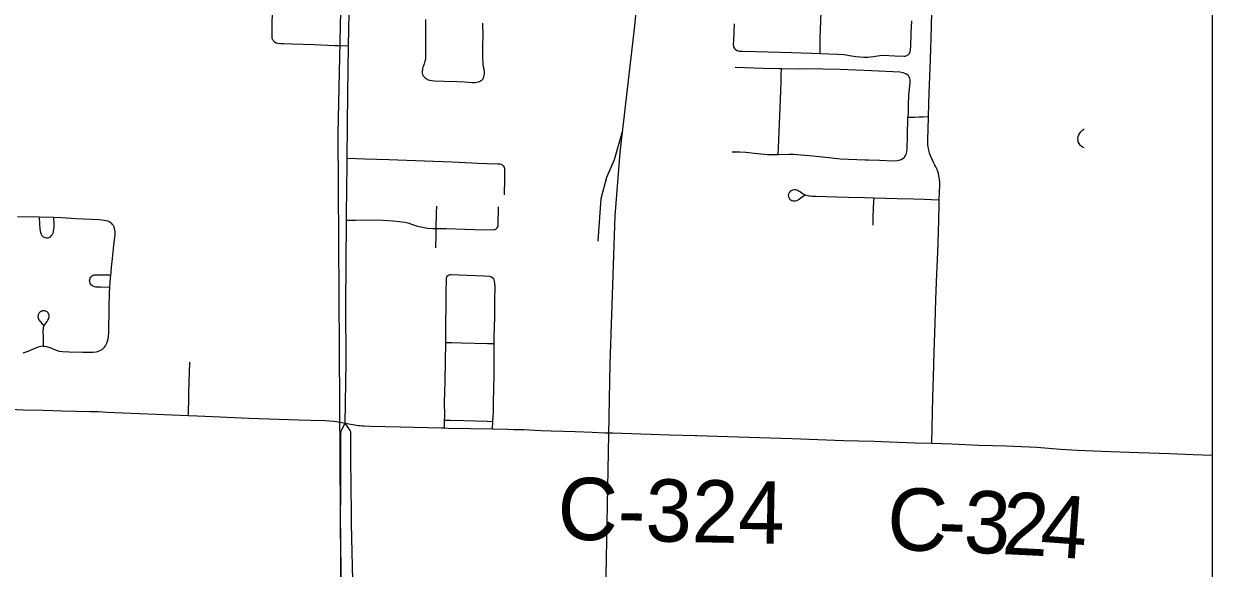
# Model space of a CAD drawing. Extents: x 0 to 680, y 0 to 834.
# Drawn here: x 333.07 to 374.69, y 304.51 to 323.58 of the extents above; entities that cross this region are included whole.
import ezdxf

# ---------------------------------------------------------------- set-up
doc = ezdxf.new("R2010")
doc.units = 0
for name, color, linetype in [('GM_X_City_Street', 7, 'Continuous'), ('GM_X_County_Road', 7, 'Continuous'), ('GM_X_County_Road_Text', 7, 'Continuous'), ('GM_X_Interstate_Route', 7, 'Continuous'), ('GM_X_Rail_Line', 7, 'Continuous'), ('GM_X_State_Route', 7, 'Continuous'), ('GM_X_Township_Road', 7, 'Continuous')]:
    doc.layers.add(name, color=color, linetype=linetype)

msp = doc.modelspace()

# ---------------------------------------------------------------- linework, layer by layer
at = {"layer": 'GM_X_City_Street'}
msp.add_line((349.484, 309.392), (349.498, 309.654), dxfattribs=at)
for points in [[(341.845, 322.952), (341.801, 323.003), (341.774, 323.072), (341.767, 323.369), (341.784, 324.176), (341.815, 326.865), (341.835, 328.239), (341.839, 328.945), (341.844, 329.857), (341.846, 330.091), (341.862, 331.48), (341.871, 332.295), (341.875, 332.64), (341.879, 332.87), (341.887, 333.375), (341.899, 334.247), (341.902, 334.632), (341.906, 335.049), (341.909, 335.561), (341.912, 336.218), (341.913, 336.483), (341.914, 336.768), (341.916, 337.086)], [(360.96, 322.546), (360.959, 322.758), (360.956, 323.091), (360.993, 323.974), (361.015, 324.19), (361.057, 324.359), (361.096, 324.498)], [(364.869, 308.894), (364.911, 310.503), (364.928, 311.208), (364.951, 312.087), (364.985, 313.089), (365.01, 313.924), (365.046, 314.825), (365.077, 315.585), (365.101, 316.276), (365.128, 317.208), (365.134, 317.419), (365.149, 317.945), (365.147, 318.039), (365.137, 318.144), (365.122, 318.249), (365.103, 318.336), (365.056, 318.476), (365.012, 318.572), (364.979, 318.635), (364.947, 318.699), (364.894, 318.806), (364.836, 318.939), (364.794, 319.052), (364.78, 319.1), (364.762, 319.171), (364.745, 319.267), (364.736, 319.365), (364.732, 319.486), (364.743, 319.94), (364.751, 320.251), (364.754, 320.335), (364.772, 320.776), (364.784, 321.158), (364.828, 322.332), (364.864, 323.472), (364.878, 323.997)], [(347.137, 323.733), (347.138, 323.435), (347.135, 323.181), (347.138, 322.752), (347.142, 322.537), (347.141, 322.418), (347.134, 322.347), (347.121, 322.276), (347.109, 322.23), (347.093, 322.185), (347.068, 322.115), (347.05, 322.066), (347.037, 322.021), (347.028, 321.976), (347.023, 321.933), (347.021, 321.896), (347.024, 321.849), (347.037, 321.803), (347.059, 321.761), (347.089, 321.724), (347.123, 321.69), (347.161, 321.662), (347.202, 321.637), (347.246, 321.618), (347.291, 321.604), (347.362, 321.593), (347.457, 321.588), (347.791, 321.579), (348.231, 321.563), (348.505, 321.547), (348.768, 321.533), (348.863, 321.531), (348.935, 321.536), (348.981, 321.547), (349.026, 321.563), (349.068, 321.585), (349.107, 321.613), (349.141, 321.647), (349.168, 321.686), (349.187, 321.729), (349.199, 321.775), (349.205, 321.823), (349.204, 321.894), (349.191, 321.989), (349.172, 322.081), (349.161, 322.154), (349.154, 322.232), (349.147, 322.367), (349.151, 322.582), (349.152, 322.83), (349.153, 323.154), (349.145, 323.607)], [(357.954, 323.588), (357.924, 322.992), (357.919, 322.848), (357.93, 322.778), (357.962, 322.715), (357.996, 322.682), (358.057, 322.647), (358.125, 322.628), (358.245, 322.621), (358.722, 322.614), (359.963, 322.581), (360.654, 322.559), (360.96, 322.546)], [(360.96, 322.546), (361.583, 322.521), (361.807, 322.503), (361.986, 322.476), (362.209, 322.437), (362.352, 322.422), (362.494, 322.418), (362.631, 322.418), (362.816, 322.437), (363.051, 322.476), (363.17, 322.481), (363.575, 322.466), (363.886, 322.446), (363.933, 322.449), (363.979, 322.461), (364.04, 322.496), (364.086, 322.549), (364.116, 322.614), (364.131, 322.684), (364.134, 322.804), (364.152, 323.252), (364.167, 323.685)], [(341.845, 322.952), (341.906, 322.92), (341.971, 322.902), (342.073, 322.892), (342.161, 322.889), (342.459, 322.879), (343.237, 322.853), (343.957, 322.827), (344.077, 322.822), (344.44, 322.806)], [(357.987, 322.068), (358.964, 322.028), (359.513, 322.014), (359.609, 322.013)], [(359.492, 319.01), (359.503, 319.242), (359.53, 319.812), (359.576, 320.93), (359.59, 321.549), (359.601, 321.811), (359.609, 322.013)], [(359.609, 322.013), (360.228, 322.009), (360.443, 322.017), (361.659, 321.997), (362.756, 321.948), (363.757, 321.896), (363.852, 321.881), (363.92, 321.859), (363.984, 321.826), (364.038, 321.78), (364.067, 321.743), (364.094, 321.678), (364.105, 321.607), (364.103, 321.511), (364.061, 321.083), (364.041, 320.75), (364.041, 320.487), (364.035, 320.308)], [(359.492, 319.01), (359.88, 319.016), (360.023, 319.012), (360.284, 318.991), (360.712, 318.957), (361.375, 318.883), (361.659, 318.859), (362.54, 318.823), (362.659, 318.818), (363.04, 318.809), (363.54, 318.788), (363.66, 318.793), (363.73, 318.806), (363.796, 318.831), (363.857, 318.868), (363.91, 318.916), (363.951, 318.973), (363.98, 319.038), (363.997, 319.108), (364.006, 319.203), (364.026, 319.65), (364.035, 320.308)], [(364.035, 320.308), (364.186, 320.318), (364.276, 320.318), (364.429, 320.319), (364.572, 320.326), (364.754, 320.335)], [(370.202, 319.24), (370.15, 319.257), (370.107, 319.292), (370.066, 319.334), (370.029, 319.388), (370.003, 319.451), (369.993, 319.508), (369.991, 319.567), (370.003, 319.632), (370.02, 319.7), (370.052, 319.752), (370.086, 319.795), (370.15, 319.852), (370.18, 319.882), (370.202, 319.91)], [(344.394, 318.877), (344.713, 318.863), (345.011, 318.849), (345.849, 318.825), (347.105, 318.785), (348.061, 318.743), (348.763, 318.714), (348.966, 318.705), (349.294, 318.692), (349.667, 318.679), (349.743, 318.673), (349.812, 318.65), (349.859, 318.614), (349.891, 318.565), (349.907, 318.508), (349.911, 318.448), (349.908, 318.152), (349.902, 317.911), (349.894, 317.834), (349.896, 317.791), (349.896, 317.733), (349.896, 317.592)], [(357.884, 319.097), (358.146, 319.102), (358.36, 319.092), (358.762, 319.042), (359.118, 319.011), (359.237, 319.006), (359.492, 319.01)], [(360.427, 317.582), (360.354, 317.527), (360.298, 317.486), (360.226, 317.433), (360.179, 317.402), (360.137, 317.382), (360.091, 317.37), (360.043, 317.368), (360.019, 317.37), (359.974, 317.384), (359.932, 317.408), (359.914, 317.423), (359.885, 317.46), (359.873, 317.482), (359.859, 317.527), (359.857, 317.574), (359.864, 317.62), (359.879, 317.663), (359.905, 317.703), (359.939, 317.735), (359.981, 317.758), (360.003, 317.766), (360.05, 317.774), (360.098, 317.774), (360.145, 317.765), (360.189, 317.748), (360.23, 317.724), (360.269, 317.696), (360.347, 317.64), (360.388, 317.616), (360.432, 317.597), (360.476, 317.583), (360.52, 317.568), (360.559, 317.56), (360.595, 317.554), (360.693, 317.549), (360.821, 317.541), (361.53, 317.521), (361.954, 317.51), (362.516, 317.495), (362.847, 317.485), (363.256, 317.474), (363.66, 317.463), (364.225, 317.448), (364.615, 317.435), (364.863, 317.427), (365.134, 317.419)], [(347.514, 316.414), (347.519, 316.964), (347.53, 317.196)], [(362.814, 316.529), (362.819, 316.669), (362.823, 316.806), (362.834, 317.111), (362.842, 317.356), (362.847, 317.485)], [(333.052, 312.058), (333.218, 312.117), (333.55, 312.256), (333.609, 312.276), (333.671, 312.291), (333.733, 312.298), (333.759, 312.297), (333.797, 312.295), (333.86, 312.283), (333.979, 312.243), (334.199, 312.151), (334.309, 312.12), (334.423, 312.104), (334.659, 312.091), (335.14, 312.087), (335.367, 312.085), (335.493, 312.083), (335.605, 312.096), (335.661, 312.11), (335.714, 312.128), (335.764, 312.151), (335.811, 312.18), (335.854, 312.215), (335.893, 312.254), (335.927, 312.298), (335.956, 312.345), (335.982, 312.396), (336.018, 312.503), (336.038, 312.617), (336.05, 312.792), (336.055, 313.629), (336.072, 314.168), (336.086, 314.35), (336.1, 314.529), (336.121, 314.79), (336.124, 314.836), (336.128, 314.884), (336.143, 315.064), (336.182, 315.359), (336.224, 315.835), (336.265, 316.192), (336.269, 316.307), (336.252, 316.418), (336.234, 316.469), (336.21, 316.518), (336.179, 316.559), (336.142, 316.598), (336.1, 316.627), (336.051, 316.653), (336.001, 316.672), (335.89, 316.696), (335.713, 316.713), (334.892, 316.757), (334.386, 316.783), (334.123, 316.797), (333.604, 316.815), (332.848, 316.825)], [(333.604, 316.815), (333.619, 316.571), (333.631, 316.391), (333.641, 316.332), (333.656, 316.273), (333.676, 316.217), (333.707, 316.165), (333.749, 316.124), (333.802, 316.096), (333.861, 316.086), (333.921, 316.087), (333.969, 316.104), (334.005, 316.126), (334.034, 316.152), (334.059, 316.186), (334.09, 316.239), (334.106, 316.281), (334.115, 316.325), (334.121, 316.373), (334.13, 316.493), (334.128, 316.553), (334.123, 316.797)], [(347.514, 316.414), (347.87, 316.408), (348.513, 316.393), (348.855, 316.38), (349.524, 316.362), (349.571, 316.375), (349.598, 316.39), (349.63, 316.416), (349.654, 316.441), (349.669, 316.473), (349.679, 316.504), (349.681, 316.536), (349.684, 316.601), (349.688, 316.715), (349.692, 316.964), (349.696, 317.176)], [(344.368, 316.709), (344.691, 316.711), (344.989, 316.714), (345.644, 316.7), (346, 316.684), (346.233, 316.664), (346.408, 316.64), (346.519, 316.61), (346.686, 316.548), (346.859, 316.494), (347.034, 316.455), (347.211, 316.428), (347.39, 316.416), (347.514, 316.414)], [(347.503, 315.731), (347.513, 316.202), (347.514, 316.414)], [(336.086, 314.35), (335.779, 314.354), (335.658, 314.355), (335.593, 314.361), (335.559, 314.368), (335.527, 314.378), (335.492, 314.394), (335.466, 314.411), (335.44, 314.433), (335.415, 314.461), (335.392, 314.495), (335.382, 314.526), (335.377, 314.568), (335.375, 314.601), (335.383, 314.637), (335.395, 314.669), (335.412, 314.706), (335.431, 314.73), (335.462, 314.758), (335.494, 314.777), (335.528, 314.785), (335.563, 314.789), (335.627, 314.793), (335.689, 314.791), (336.042, 314.791), (336.121, 314.79)], [(347.852, 312.421), (347.854, 312.512), (347.851, 312.986), (347.866, 313.814), (347.86, 314.169), (347.865, 314.286), (347.87, 314.524), (347.875, 314.678), (347.891, 314.726), (347.914, 314.759)], [(347.914, 314.759), (347.946, 314.781), (348, 314.8), (348.041, 314.806), (348.6, 314.784), (349.178, 314.761), (349.377, 314.741), (349.465, 314.707), (349.516, 314.679)], [(349.547, 312.384), (349.547, 312.595), (349.562, 313.314), (349.571, 313.897), (349.58, 314.38), (349.561, 314.579), (349.546, 314.631), (349.516, 314.679)], [(333.759, 312.297), (333.755, 312.607), (333.752, 312.841), (333.755, 312.9), (333.765, 312.957), (333.785, 313.012), (333.813, 313.063), (333.885, 313.156), (333.917, 313.205), (333.941, 313.258), (333.954, 313.315), (333.956, 313.34), (333.954, 313.374), (333.948, 313.399), (333.937, 313.43), (333.92, 313.456), (333.904, 313.477), (333.886, 313.495), (333.857, 313.511), (333.829, 313.523), (333.801, 313.53), (333.774, 313.532), (333.743, 313.531), (333.713, 313.523), (333.687, 313.513), (333.658, 313.499), (333.63, 313.478), (333.609, 313.454), (333.593, 313.432), (333.581, 313.411), (333.574, 313.385), (333.567, 313.327), (333.576, 313.269), (333.599, 313.215), (333.651, 313.144), (333.715, 313.074), (333.769, 313.032)], [(347.809, 309.703), (347.814, 309.831), (347.809, 310.37), (347.814, 310.631), (347.825, 311.092), (347.852, 312.421)], [(347.852, 312.421), (348.045, 312.419), (348.392, 312.414), (349.316, 312.39), (349.547, 312.384)], [(349.498, 309.654), (349.515, 309.988), (349.524, 310.329), (349.538, 311.291), (349.546, 312.003), (349.547, 312.384)], [(338.833, 309.863), (338.837, 310.033), (338.845, 310.372), (338.853, 310.679), (338.876, 311.367), (338.889, 311.735)], [(347.809, 309.703), (348.008, 309.698), (348.487, 309.684), (349.301, 309.663), (349.498, 309.654)], [(347.809, 309.427), (347.809, 309.575), (347.809, 309.703)]]:
    msp.add_lwpolyline(points, dxfattribs=at)
at = {"layer": 'GM_X_County_Road'}
for points in [[(344.326, 309.597), (344.788, 309.517), (344.856, 309.507), (344.918, 309.5), (344.982, 309.496), (345.206, 309.49), (346.268, 309.462), (347.694, 309.43), (347.809, 309.427)], [(347.809, 309.427), (347.935, 309.425), (349.484, 309.392)], [(349.484, 309.392), (350.013, 309.381), (350.24, 309.377)], [(350.24, 309.377), (350.586, 309.367), (351.182, 309.341), (351.539, 309.329), (352.379, 309.299), (352.976, 309.276), (353.431, 309.257)], [(353.431, 309.257), (353.522, 309.258), (353.654, 309.252), (353.689, 309.252)], [(353.689, 309.252), (354.012, 309.244), (355.684, 309.191), (356.578, 309.167), (356.609, 309.167)], [(356.609, 309.167), (356.64, 309.166), (358.073, 309.117), (359.985, 309.057), (361.776, 308.992), (362.851, 308.959), (363.392, 308.939)], [(363.392, 308.939), (364.284, 308.905), (364.869, 308.894)], [(364.869, 308.894), (365.569, 308.865), (366.522, 308.825), (367.476, 308.796), (368.547, 308.751), (369.379, 308.689), (369.975, 308.652), (370.81, 308.617), (372.12, 308.569), (373.193, 308.533), (374.027, 308.497), (374.693, 308.475)]]:
    msp.add_lwpolyline(points, dxfattribs=at)
at = {"layer": 'GM_X_Interstate_Route'}
msp.add_lwpolyline([(44.693, 394.069), (374.693, 394.069), (374.693, 64.069), (44.693, 64.069)], close=True, dxfattribs=at)
at = {"layer": 'GM_X_Rail_Line'}
for points in [[(351.218, 64.069), (351.448, 90.121), (351.798, 116.184), (351.86, 139.423), (352.175, 154.252), (352.451, 189.912), (352.901, 229.863), (353.003, 247.107), (353.355, 298.069), (353.602, 311.675), (353.78, 316.856), (353.954, 319.076), (354.473, 323.516), (355.976, 338.772), (356.265, 341.847), (356.561, 344.985), (356.644, 347.076), (356.685, 349.146), (356.788, 357.395), (356.901, 372.817), (357.146, 391.252), (357.174, 394.069)], [(341.694, 64.069), (341.887, 75.733), (342.297, 152.995), (342.913, 209.384), (343.255, 230.188), (343.597, 251.334), (344.253, 291.298), (344.078, 319.736), (344.92, 358.256)], [(353.191, 315.972), (353.293, 317.461), (353.493, 318.215), (353.762, 318.826), (354.04, 319.812)]]:
    msp.add_lwpolyline(points, dxfattribs=at)
at = {"layer": 'GM_X_State_Route'}
for points in [[(344.326, 309.597), (344.36, 311.729), (344.345, 313.7), (344.368, 316.709), (344.37, 316.925), (344.391, 318.656), (344.394, 318.877), (344.422, 321.163), (344.44, 322.775), (344.44, 322.806), (344.493, 325.114), (344.527, 326.655), (344.545, 327.79), (344.563, 328.317), (344.581, 328.785), (344.588, 329.554)], [(344.067, 293.923), (344.076, 294.353), (344.096, 295.968), (344.136, 298.718), (344.144, 299.854), (344.147, 300.076), (344.149, 300.225), (344.172, 301.883), (344.182, 304.215), (344.173, 305.591), (344.158, 306.248), (344.168, 307.206), (344.172, 308.134), (344.177, 309.109), (344.177, 309.227), (344.181, 309.284), (344.19, 309.323), (344.211, 309.373), (344.326, 309.597)], [(344.548, 306.428), (344.527, 308.347), (344.529, 308.976), (344.529, 309.215), (344.525, 309.26), (344.518, 309.295), (344.503, 309.337), (344.474, 309.378), (344.326, 309.597)], [(344.492, 292.464), (344.507, 293.904), (344.54, 296.132), (344.543, 297.562), (344.58, 300.049), (344.582, 300.211), (344.599, 301.317), (344.609, 302.27), (344.602, 303.58), (344.552, 306.082), (344.548, 306.428)]]:
    msp.add_lwpolyline(points, dxfattribs=at)
at = {"layer": 'GM_X_Township_Road'}
for points in [[(332.355, 310.093), (333.062, 310.066), (333.748, 310.047), (334.409, 310.028), (335.386, 310.008), (335.673, 309.999), (335.974, 309.985), (338.833, 309.863)], [(338.833, 309.863), (338.858, 309.862), (339.689, 309.825), (340.956, 309.767), (342.688, 309.713), (343.114, 309.7), (343.628, 309.684), (343.778, 309.679), (343.912, 309.668), (344.022, 309.654), (344.326, 309.597)]]:
    msp.add_lwpolyline(points, dxfattribs=at)

# ---------------------------------------------------------------- texts
at = {"layer": 'GM_X_County_Road_Text'}
for s, height, rotation, p in [('C-324', 2.1818, 358.8957, (351.75, 305.519)), ('C', 2.182, 357.8451, (363.278, 305.168)), ('3', 2.182, 357.694, (365.963, 305.067)), ('2', 2.182, 357.1628, (367.301, 305.013)), ('4', 2.182, 355.7809, (368.629, 304.947)), ('-', 2.182, 357.8139, (365.069, 305.101))]:
    msp.add_text(s, height=height, rotation=rotation, dxfattribs=at).set_placement(p)

doc.saveas('drawing.dxf')
